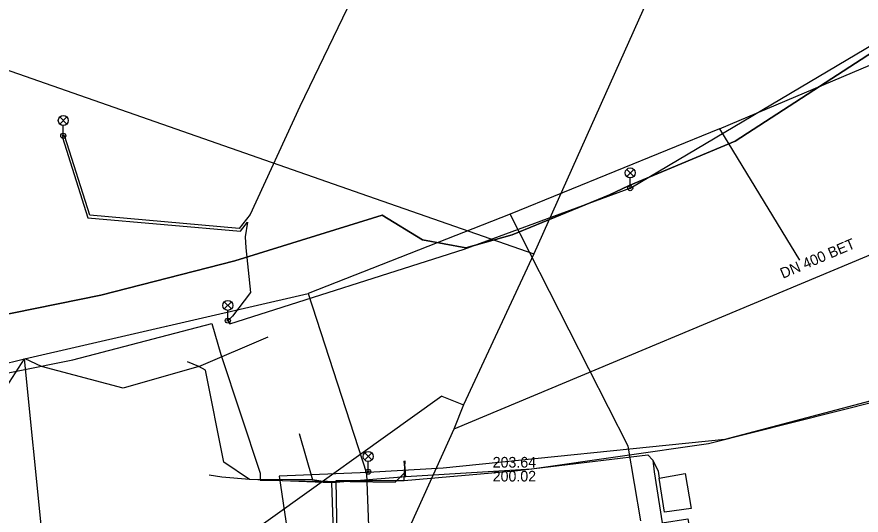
# Model space of a CAD drawing. Extents: x -596228 to -595156, y -1161235 to -1159373.
# Drawn here: x -595769 to -595705.3, y -1160336 to -1160298.5 of the extents above; entities that cross this region are included whole.
import ezdxf

# ---------------------------------------------------------------- set-up
doc = ezdxf.new("R2010")
doc.units = 0
for name, color, linetype in [('Vrstva 1', 7, 'Continuous'), ('Vrstva 12', 7, 'Continuous'), ('Vrstva 33', 7, 'Continuous'), ('Vrstva 42', 7, 'Continuous'), ('Vrstva 54', 7, 'Continuous'), ('Vrstva 55', 7, 'Continuous'), ('Vrstva 9', 7, 'Continuous')]:
    doc.layers.add(name, color=color, linetype=linetype)

msp = doc.modelspace()

# ---------------------------------------------------------------- linework, layer by layer
at = {"layer": 'Vrstva 1'}
for q in [(-595755.67, -1160340.44), (-595735.3, -1160327.71)]:
    msp.add_line((-595736.93, -1160327.05), q, dxfattribs=at)
at = {"layer": 'Vrstva 33'}
for p, q in [((-595765.755, -1160306.005), (-595765.225, -1160306.535)), ((-595765.755, -1160306.535), (-595765.225, -1160306.005)), ((-595765.49, -1160307.42), (-595765.49, -1160306.645)), ((-595722.995, -1160309.955), (-595722.465, -1160310.485)), ((-595722.995, -1160310.485), (-595722.465, -1160309.955)), ((-595722.73, -1160311.37), (-595722.73, -1160310.595)), ((-595753.345, -1160319.945), (-595752.815, -1160320.475)), ((-595753.345, -1160320.475), (-595752.815, -1160319.945)), ((-595753.08, -1160321.36), (-595753.08, -1160320.585)), ((-595742.756, -1160331.332), (-595742.226, -1160331.862)), ((-595742.756, -1160331.862), (-595742.226, -1160331.332)), ((-595742.491, -1160332.747), (-595742.491, -1160331.972))]:
    msp.add_line(p, q, dxfattribs=at)
for centre, radius in [((-595765.49, -1160306.27), 0.375), ((-595765.49, -1160307.42), 0.19), ((-595765.49, -1160307.42), 0.05), ((-595722.73, -1160310.22), 0.375), ((-595722.73, -1160311.37), 0.19), ((-595722.73, -1160311.37), 0.05), ((-595753.08, -1160320.21), 0.375), ((-595753.08, -1160321.36), 0.19), ((-595753.08, -1160321.36), 0.05), ((-595742.491, -1160331.597), 0.375), ((-595742.491, -1160332.747), 0.19), ((-595742.491, -1160332.747), 0.05)]:
    msp.add_circle(centre, radius, dxfattribs=at)
at = {"layer": 'Vrstva 42'}
for p, q in [((-595755.26, -1160324.82), (-595750.039, -1160322.58)), ((-595747.696, -1160329.86), (-595746.687, -1160333.353)), ((-595739.78, -1160333.4), (-595739.71, -1160331.935))]:
    msp.add_line(p, q, dxfattribs=at)
for points in [[(-595847.13, -1160313.44), (-595833.42, -1160315.69), (-595818.81, -1160318.02), (-595804.19, -1160320.42), (-595787.39, -1160322.98), (-595780.95, -1160322.96), (-595774.21, -1160321.77), (-595762.67, -1160319.43), (-595752.552, -1160316.857), (-595741.43, -1160313.41), (-595738.39, -1160315.27), (-595735.13, -1160315.87), (-595731.62, -1160314.9), (-595724.29, -1160311.87), (-595722.868, -1160311.197), (-595714.82, -1160307.83), (-595703.02, -1160300.19), (-595693.78, -1160291.95), (-595681.58, -1160277.83), (-595677.955, -1160273.423), (-595678.45, -1160273.05)], [(-595847.13, -1160313.44), (-595833.42, -1160315.69), (-595818.81, -1160318.02), (-595804.19, -1160320.42), (-595787.39, -1160322.98), (-595780.95, -1160322.96), (-595774.21, -1160321.77), (-595762.67, -1160319.43), (-595752.552, -1160316.857), (-595741.43, -1160313.41), (-595738.39, -1160315.27), (-595735.13, -1160315.87), (-595731.62, -1160314.9), (-595724.29, -1160311.87), (-595722.868, -1160311.197), (-595714.82, -1160307.83), (-595703.02, -1160300.19), (-595693.78, -1160291.95), (-595681.58, -1160277.83), (-595677.955, -1160273.423), (-595678.45, -1160273.05)], [(-595678.45, -1160273.05), (-595677.955, -1160273.423), (-595681.58, -1160277.83), (-595693.78, -1160291.95), (-595703.02, -1160300.19), (-595714.82, -1160307.83), (-595722.868, -1160311.197), (-595724.29, -1160311.87), (-595731.62, -1160314.9), (-595735.13, -1160315.87), (-595738.39, -1160315.27), (-595741.43, -1160313.41), (-595752.552, -1160316.857), (-595762.67, -1160319.43), (-595774.21, -1160321.77), (-595780.95, -1160322.96), (-595787.39, -1160322.98), (-595804.19, -1160320.42), (-595818.81, -1160318.02), (-595833.42, -1160315.69), (-595847.13, -1160313.44)], [(-595847.13, -1160313.44), (-595833.42, -1160315.69), (-595818.81, -1160318.02), (-595804.19, -1160320.42), (-595787.39, -1160322.98), (-595780.95, -1160322.96), (-595774.21, -1160321.77), (-595762.67, -1160319.43), (-595752.552, -1160316.857), (-595741.43, -1160313.41), (-595738.39, -1160315.27), (-595735.13, -1160315.87), (-595731.62, -1160314.9), (-595724.29, -1160311.87), (-595722.868, -1160311.197), (-595714.82, -1160307.83), (-595703.02, -1160300.19), (-595693.78, -1160291.95), (-595681.58, -1160277.83), (-595677.955, -1160273.423)], [(-595847.13, -1160313.44), (-595833.42, -1160315.69), (-595818.81, -1160318.02), (-595804.19, -1160320.42), (-595787.39, -1160322.98), (-595780.95, -1160322.96), (-595774.21, -1160321.77), (-595762.67, -1160319.43), (-595752.552, -1160316.857), (-595741.43, -1160313.41), (-595738.39, -1160315.27), (-595735.13, -1160315.87), (-595731.62, -1160314.9), (-595724.29, -1160311.87), (-595722.868, -1160311.197), (-595714.82, -1160307.83), (-595703.02, -1160300.19), (-595693.78, -1160291.95), (-595681.58, -1160277.83), (-595677.955, -1160273.423)], [(-595847.13, -1160313.44), (-595833.42, -1160315.69), (-595818.81, -1160318.02), (-595804.19, -1160320.42), (-595787.39, -1160322.98), (-595780.95, -1160322.96), (-595774.21, -1160321.77), (-595762.67, -1160319.43), (-595752.552, -1160316.857), (-595741.43, -1160313.41), (-595738.39, -1160315.27), (-595735.13, -1160315.87), (-595731.62, -1160314.9), (-595724.29, -1160311.87), (-595722.868, -1160311.197), (-595714.82, -1160307.83), (-595703.02, -1160300.19), (-595693.78, -1160291.95), (-595681.58, -1160277.83), (-595677.955, -1160273.423)], [(-595847.13, -1160313.44), (-595833.42, -1160315.69), (-595818.81, -1160318.02), (-595804.19, -1160320.42), (-595787.39, -1160322.98), (-595780.95, -1160322.96), (-595774.21, -1160321.77), (-595762.67, -1160319.43), (-595752.552, -1160316.857), (-595741.43, -1160313.41), (-595738.39, -1160315.27), (-595735.13, -1160315.87), (-595731.62, -1160314.9), (-595724.29, -1160311.87), (-595722.868, -1160311.197), (-595714.82, -1160307.83), (-595703.02, -1160300.19), (-595693.78, -1160291.95), (-595681.58, -1160277.83), (-595677.955, -1160273.423)], [(-595895.894, -1160304.949), (-595895.931, -1160305.565), (-595896.41, -1160308.706), (-595893.65, -1160309.078), (-595880.587, -1160311.231), (-595867.748, -1160313.527), (-595860.217, -1160314.981), (-595847.991, -1160316.922), (-595834.216, -1160319.371), (-595820.364, -1160321.5), (-595806.264, -1160323.708), (-595792.142, -1160326.114), (-595783.529, -1160327.233), (-595777.032, -1160326.773), (-595764.779, -1160324.315), (-595754.282, -1160321.569), (-595753.606, -1160323.921), (-595750.637, -1160332.868), (-595750.632, -1160333.38), (-595740.462, -1160333.548), (-595739.673, -1160332.748), (-595739.749, -1160331.939)], [(-595661.84, -1160310.55), (-595672.63, -1160315.73), (-595674.02, -1160316.87), (-595682.65, -1160319.88), (-595696.41, -1160325.14), (-595701.61, -1160327.25), (-595703.94, -1160327.4), (-595716.82, -1160330.64), (-595730.14, -1160332.55), (-595739.66, -1160333.13), (-595739.784, -1160331.942)], [(-595661.84, -1160310.55), (-595672.63, -1160315.73), (-595674.02, -1160316.87), (-595682.65, -1160319.88), (-595696.41, -1160325.14), (-595701.61, -1160327.25), (-595703.94, -1160327.4), (-595716.82, -1160330.64), (-595730.14, -1160332.55), (-595739.66, -1160333.13), (-595739.784, -1160331.942)], [(-595661.84, -1160310.55), (-595672.63, -1160315.73), (-595674.02, -1160316.87), (-595682.65, -1160319.88), (-595696.41, -1160325.14), (-595701.61, -1160327.25), (-595703.94, -1160327.4), (-595716.82, -1160330.64), (-595730.14, -1160332.55), (-595739.66, -1160333.13), (-595739.784, -1160331.942)], [(-595661.84, -1160310.55), (-595672.63, -1160315.73), (-595674.02, -1160316.87), (-595682.65, -1160319.88), (-595696.41, -1160325.14), (-595701.61, -1160327.25), (-595703.94, -1160327.4), (-595716.82, -1160330.64), (-595730.14, -1160332.55), (-595739.66, -1160333.13), (-595739.784, -1160331.942)], [(-595755.26, -1160324.82), (-595760.97, -1160326.46), (-595767.13, -1160324.81), (-595768.37, -1160324.24)], [(-595755.26, -1160324.82), (-595760.97, -1160326.46), (-595767.13, -1160324.81), (-595768.37, -1160324.24)], [(-595751.44, -1160333.33), (-595753.39, -1160332.04), (-595754.76, -1160325.09), (-595755.26, -1160324.82), (-595756.12, -1160324.46)], [(-595751.44, -1160333.33), (-595753.39, -1160332.04), (-595754.76, -1160325.09), (-595755.26, -1160324.82)], [(-595786.51, -1160340.81), (-595785.62, -1160339.97), (-595784.43, -1160339.54), (-595772.55, -1160341.27), (-595759.72, -1160342.74), (-595753.29, -1160343.01), (-595746.78, -1160343.15), (-595744.71, -1160344.54), (-595744.9, -1160333.41), (-595739.78, -1160333.4), (-595731.42, -1160332.67), (-595721.4, -1160331.47), (-595721.02, -1160331.89), (-595720.93, -1160332.76), (-595720.32, -1160336.61), (-595718.38, -1160336.3), (-595717.93, -1160338.83), (-595719.88, -1160339.16), (-595720.32, -1160336.61)], [(-595721.02, -1160331.89), (-595720.63, -1160332.71), (-595720.55, -1160333.23), (-595718.58, -1160332.89), (-595718.13, -1160335.52), (-595720.15, -1160335.81), (-595720.55, -1160333.23)], [(-595739.66, -1160333.13), (-595745.26, -1160333.59), (-595746.687, -1160333.353), (-595751.44, -1160333.33), (-595753.53, -1160333.17), (-595754.49, -1160333)], [(-595739.66, -1160333.13), (-595745.26, -1160333.59), (-595751.44, -1160333.33), (-595753.53, -1160333.17), (-595754.49, -1160333)], [(-595745.26, -1160333.59), (-595744.9, -1160343.88), (-595746.77, -1160343.07), (-595753.64, -1160343.06), (-595755.62, -1160342.89), (-595756.32, -1160342.9), (-595756.08, -1160343.74), (-595755.49, -1160344.07)]]:
    msp.add_lwpolyline(points, dxfattribs=at)
at = {"layer": 'Vrstva 54'}
for p, q in [((-595716, -1160306.91), (-595698.72, -1160299.57)), ((-595716, -1160306.91), (-595731.79, -1160313.32)), ((-595716, -1160306.91), (-595709.96, -1160316.79)), ((-595731.79, -1160313.32), (-595747.01, -1160319.31)), ((-595722.87, -1160330.83), (-595731.79, -1160313.32)), ((-595768.42, -1160324.25), (-595747.01, -1160319.31)), ((-595747.01, -1160319.31), (-595742.62, -1160332.85)), ((-595786.71, -1160328.54), (-595768.42, -1160324.25)), ((-595773.12, -1160331.49), (-595768.42, -1160324.25)), ((-595767.03, -1160337.91), (-595768.42, -1160324.25)), ((-595721.93, -1160336.45), (-595722.87, -1160330.83)), ((-595742.62, -1160332.85), (-595742.41, -1160338.66))]:
    msp.add_line(p, q, dxfattribs=at)
at = {"layer": 'Vrstva 55'}
for points in [[(-595753.08, -1160321.36), (-595752.925, -1160321.596), (-595735.26, -1160315.97), (-595722.68, -1160311.35), (-595704.28, -1160300.44), (-595687.656, -1160284.282), (-595687.61, -1160283.8)], [(-595743.71, -1160297.02), (-595747.66, -1160305.22), (-595751.39, -1160313.347), (-595752.225, -1160314.416), (-595763.495, -1160313.416), (-595765.365, -1160307.485), (-595765.49, -1160307.42), (-595765.555, -1160307.545), (-595763.645, -1160313.604), (-595752.135, -1160314.624), (-595751.599, -1160313.94), (-595751.76, -1160315.04), (-595751.73, -1160315.87), (-595751.36, -1160319.24), (-595752.72, -1160321.03), (-595753.08, -1160321.36)], [(-595641.433, -1160297.27), (-595641.28, -1160297.69), (-595642.79, -1160301.95), (-595645.8, -1160305.22), (-595683.45, -1160320.78), (-595697.51, -1160325.55), (-595715.58, -1160330.31), (-595736.829, -1160332.482), (-595742.491, -1160332.8), (-595749.21, -1160333.08), (-595745.95, -1160355.16), (-595741.43, -1160359.18), (-595737.41, -1160363.19), (-595735.15, -1160369.47), (-595738.78, -1160371.82), (-595739.832, -1160372.258)]]:
    msp.add_lwpolyline(points, dxfattribs=at)
at = {"layer": 'Vrstva 9'}
for p, q in [((-595774.127, -1160300.914), (-595743.039, -1160311.769)), ((-595743.039, -1160311.769), (-595729.99, -1160316.32)), ((-595696.26, -1160312.9), (-595736.02, -1160329.55)), ((-595729.99, -1160316.32), (-595735.3, -1160327.71)), ((-595735.3, -1160327.71), (-595736.02, -1160329.55))]:
    msp.add_line(p, q, dxfattribs=at)
for points in [[(-595714.83, -1160282.43), (-595716.382, -1160285.899), (-595729.99, -1160316.32)], [(-595736.02, -1160329.55), (-595743.422, -1160345.88), (-595745.697, -1160350.898), (-595747.91, -1160355.78)]]:
    msp.add_lwpolyline(points, dxfattribs=at)

# ---------------------------------------------------------------- texts
at = {"layer": 'Vrstva 12'}
msp.add_text('DN 400 BET', height=0.8, rotation=23, dxfattribs=at).set_placement((-595711.213, -1160318.208))
for s, p in [('203.64', (-595733.1, -1160332.435)), ('200.02', (-595733.1, -1160333.485))]:
    msp.add_text(s, height=0.8, dxfattribs=at).set_placement(p)

doc.saveas('drawing.dxf')
